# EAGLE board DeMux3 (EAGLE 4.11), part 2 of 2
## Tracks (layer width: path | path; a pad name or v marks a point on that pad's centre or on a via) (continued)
N$50  (via drill 0.61) (continued)
  Top 0.381: v198.75,48.9 198.75,90.81 v199.39,91.44
  Bottom 0.381: v198.75,48.9 216.53,48.9 217.81,50.16 IC9.5 | v199.39,91.44 202.56,91.44 205.1,93.98 R72.1
N$51  (via drill 0.61)
  Top 0.381: v198.12,47.62 197.49,48.26 v197.49,91.44
  Bottom 0.381: v198.12,47.62 217.81,47.62 220.34,50.16 IC9.6 | v197.49,91.44 198.75,92.71 201.29,92.71 202.56,93.98 R73.1
N$52  (via drill 0.61)
  Top 0.381: v300.99,97.16 303.53,94.61 303.53,90.81 304.8,89.53 R16.2 | v257.81,102.87 257.81,128.91 259.08,130.18 IDE.31
  Bottom 0.381: v300.99,97.16 299.08,99.06 292.74,99.06 292.1,99.69 292.1,102.87 v257.81,102.87
N$53  (via drill 0.61)
  Top 0.381: v302.26,119.38 302.26,116.84 306.07,113.03 306.07,93.34 304.8,92.08 R15.2 | v266.7,122.56 264.16,125.09 264.16,130.18 IDE.27
  Bottom 0.381: v302.26,119.38 299.08,122.56 v266.7,122.56
N$54  (via drill 0.61)
  Top 0.381: v300.99,125.09 300.99,116.84 303.53,114.3 303.53,95.89 304.8,94.61 R14.2 | v268.61,128.27 266.7,130.18 IDE.25
  Bottom 0.381: v300.99,125.09 297.81,128.27 v268.61,128.27
N$55  (via drill 0.61)
  Top 0.381: v302.26,109.86 v302.26,97.79 | v270.51,114.3 270.51,128.91 269.24,130.18 IDE.23
  Bottom 0.381: v302.26,97.79 302.89,97.79 304.17,96.52 R13.2 | v302.26,109.86 297.81,114.3 v270.51,114.3
N$56  (via drill 0.61)
  Top 0.381: v300.99,99.06 300.99,111.12 300.36,111.76 300.36,114.94 299.72,115.57 299.72,128.91 300.36,129.54 v300.36,130.81
  Bottom 0.381: v300.99,99.06 304.17,99.06 R12.2 | v300.36,130.81 299.08,132.08 273.69,132.08 272.42,130.81 IDE.21
N$57  (via drill 0.61)
  Top 0.381: v197.49,45.72 196.22,46.99 v196.22,75.56 | v200.03,79.38 200.66,80.01 200.66,93.34 R74.1
  Bottom 0.381: v197.49,45.72 218.44,45.72 222.88,50.16 IC9.7 | v196.22,75.56 v200.03,79.38
N$58  (via drill 0.61)
  Top 0.381: v245.11,123.19 245.11,93.34 250.19,88.27 250.19,71.12 248.92,69.85 IC12.7 | v317.5,129.54 320.04,132.08 320.04,133.99 R97.1
  Bottom 0.381: v245.11,123.19 249.56,127.64 266.06,127.64 267.97,129.54 v317.5,129.54
N$59  (via drill 0.61)
  Top 0.381: v242.57,85.09 242.57,74.93 243.84,73.66 243.84,69.85 IC12.5
  Bottom 0.381: v242.57,85.09 242.57,87.63 233.04,87.63 226.69,93.98 R96.1
N$60  (via drill 0.61)
  Top 0.381: v241.3,64.14 241.3,67.31 IC12.4 | v246.38,64.14 247.65,65.41 v247.65,83.82
  Bottom 0.381: v241.3,64.14 v246.38,64.14 | v247.65,83.82 238.76,92.71 230.5,92.71 229.24,93.98 R95.1
N$61  (via drill 0.61)
  Top 0.381: v236.22,71.75 236.22,71.12 234.95,69.85 234.95,66.67 236.85,66.67 238.12,67.94 IC12.3 | v231.14,71.75 232.41,73.03 232.41,90.17 231.14,91.44 231.14,93.34 R94.1
  Bottom 0.381: v236.22,71.75 v231.14,71.75
N$62
  Top 0.381: IC12.2 236.22,69.85 237.49,71.12 237.49,94.61 236.85,95.25 233.68,95.25 233.68,94.61 R93.1
N$63
  Top 0.381: IC12.1 233.68,69.85 234.95,71.12 234.95,92.08 236.22,93.34 R92.1
N$64  (via drill 0.61)
  Top 0.381: v236.22,80.64 236.22,77.47 IC12.15 | v241.3,85.72 241.94,86.36 241.94,129.54 236.85,134.62 R91.1
  Bottom 0.381: v236.22,80.64 237.49,81.92 237.49,85.72 v241.3,85.72
N$65  (via drill 0.61)
  Top 0.381: v209.55,95.25 209.55,93.34 210.82,92.08 210.82,77.47 IC10.15
  Bottom 0.381: v209.55,95.25 200.03,95.25 198.75,93.98 R75.1
N$66  (via drill 0.61)
  Top 0.381: v209.55,88.9 209.55,71.12 208.28,69.85 IC10.1
  Bottom 0.381: v209.55,88.9 194.31,88.9 193.68,89.53 193.68,93.98 194.94,93.98 R76.1
N$67  (via drill 0.61)
  Top 0.381: v210.82,73.66 210.82,69.85 IC10.2 | v214.63,74.3 214.63,95.89 207.01,103.5 207.01,132.72 208.28,133.99 R77.1
  Bottom 0.381: v210.82,73.66 211.46,74.3 v214.63,74.3
N$68  (via drill 0.61)
  Top 0.381: v213.36,65.41 213.36,67.31 IC10.3 | v193.68,65.41 v193.68,107.95 | v209.55,111.76 209.55,132.72 210.82,133.99 R78.1
  Bottom 0.381: v193.68,65.41 v213.36,65.41 | v193.68,107.95 197.49,111.76 v209.55,111.76
N$69  (via drill 0.61)
  Top 0.381: v192.41,66.67 v192.41,84.45 | v217.17,87.63 217.17,132.08 214.63,134.62 214,134.62 R79.1
  Bottom 0.381: v192.41,66.67 214,66.67 215.26,67.94 IC10.4 | v192.41,84.45 195.58,87.63 v217.17,87.63
N$70  (via drill 0.61)
  Top 0.381: v218.44,73.03 218.44,69.85 IC10.5 | v191.13,72.39 190.5,73.03 v190.5,121.92
  Bottom 0.381: v218.44,73.03 212.09,73.03 211.46,72.39 v191.13,72.39 | v190.5,121.92 198.75,130.18 217.17,130.18 220.98,133.99 R80.1
N$71  (via drill 0.61)
  Top 0.381: v220.98,61.59 220.98,67.31 IC10.6 | v177.8,83.19 v177.8,75.56 | v191.77,89.53 191.77,132.72 196.22,137.16 223.52,137.16 223.52,135.25 R81.1
  Bottom 0.381: v220.98,61.59 209.55,61.59 207.01,64.14 189.23,64.14 v177.8,75.56 | v177.8,83.19 184.15,89.53 v191.77,89.53
N$72
  Top 0.381: IC10.7 223.52,69.85 223.52,72.39 222.25,73.66 222.25,92.08 223.52,93.34 R82.1
N$73
  Top 0.381: R83.1 221.62,93.98 222.88,95.25 227.33,95.25 227.33,52.07 230.5,48.9 234.95,48.9 234.95,55.88 236.22,57.15 IC11.15
N$74  (via drill 0.61)
  Top 0.381: v231.14,56.52 231.14,54.61 233.68,52.07 IC11.1 | v213.36,62.87 212.09,64.14 212.09,92.08 213.36,93.34 R84.1
  Bottom 0.381: v231.14,56.52 224.79,62.87 v213.36,62.87
N$75  (via drill 0.61)
  Top 0.381: v194.94,90.17 194.94,39.37 200.66,33.66 200.66,3.17 210.82,3.17 213.36,5.71 213.36,10.79 229.87,27.3 229.87,40.64 238.76,49.53 IC11.3
  Bottom 0.381: v194.94,90.17 203.84,90.17 207.65,93.98 R86.1
N$76  (via drill 0.61)
  Top 0.381: v237.49,61.59 237.49,53.34 236.22,52.07 IC11.2 | v210.19,64.14 207.01,67.31 v207.01,90.81
  Bottom 0.381: v237.49,61.59 234.95,64.14 v210.19,64.14 | v207.01,90.81 210.19,93.98 R85.1
N$77  (via drill 0.61)
  Top 0.381: v186.69,104.14 187.96,102.87 v187.96,44.45 | v232.41,40.64 241.3,49.53 IC11.4
  Bottom 0.381: v186.69,104.14 186.69,108.58 197.49,119.38 234.95,119.38 234.95,135.25 234.31,135.89 227.97,135.89 226.69,134.62 R87.1 | v187.96,44.45 191.77,40.64 v232.41,40.64
N$78  (via drill 0.61)
  Top 0.381: v229.87,51.44 229.87,94.61 227.33,97.16 227.33,132.72 228.6,133.99 R88.1
  Bottom 0.381: v229.87,51.44 232.41,48.9 241.94,48.9 243.21,50.16 IC11.5
N$79  (via drill 0.61)
  Top 0.381: v238.12,96.52 238.12,127 231.14,133.99 R89.1 | v262.25,92.71 265.43,89.53 v265.43,58.42 | v248.92,55.24 246.38,52.7 246.38,52.07 IC11.6
  Bottom 0.381: v238.12,96.52 241.94,92.71 v262.25,92.71 | v265.43,58.42 262.89,55.88 257.18,55.88 255.91,54.61 252.73,54.61 252.09,55.24 v248.92,55.24
N$80  (via drill 0.61)
  Top 0.381: v186.69,54.61 184.15,57.15 v184.15,90.81
  Bottom 0.381: v186.69,54.61 225.43,54.61 227.33,52.7 247.01,52.7 248.28,51.44 IC11.7 | v184.15,90.81 180.97,93.98 178.44,93.98 176.53,95.89 176.53,107.95 178.44,107.95 193.68,123.19 217.81,123.19 227.97,133.35 231.78,133.35 233.04,134.62 R90.1
N$81  (via drill 0.61)
  Top 0.381: v140.97,92.08 140.97,85.09 141.6,84.45 141.6,80.64 142.24,80.01 IC8.5
  Bottom 0.381: v140.97,92.08 140.34,92.71 139.06,92.71 137.79,93.98 R127.1
N$82
  Top 0.381: IC8.4 139.7,80.01 138.43,81.28 138.43,92.08 139.7,93.34 R126.1
N$83
  Top 0.381: IC8.3 137.16,80.01 135.89,81.28 135.89,90.81 138.43,93.34 138.43,94.61 139.06,95.25 142.24,95.25 142.24,94.61 R125.1
N$84  (via drill 0.61)
  Top 0.381: v133.35,95.25 133.35,81.28 134.62,80.01 IC8.2
  Bottom 0.381: v133.35,95.25 142.88,95.25 144.15,93.98 R124.1
N$85  (via drill 0.61)
  Top 0.381: v130.81,95.89 130.81,81.28 132.08,80.01 IC8.1
  Bottom 0.381: v130.81,95.89 131.44,96.52 144.15,96.52 146.69,93.98 R123.1
N$86  (via drill 0.61)
  Top 0.381: v128.27,88.27 128.27,124.46 v136.53,132.72
  Bottom 0.381: v128.27,88.27 132.72,88.27 133.99,87 IC8.15 | v136.53,132.72 137.16,133.35 145.41,133.35 146.69,134.62 R122.1
N$87
  Top 0.381: R121.1 144.78,133.99 152.4,126.36 152.4,106.05 160.02,98.42 160.02,55.88 156.84,52.7 147.32,52.7 147.32,57.15 IC7.7
N$88  (via drill 0.61)
  Top 0.381: v148.59,84.45 148.59,87.63 149.86,88.9 149.86,126.36 142.24,133.99 R120.1 | v152.4,81.92 151.13,80.64 151.13,73.66 148.59,71.12 148.59,63.5 144.78,59.69 IC7.6
  Bottom 0.381: v148.59,84.45 149.86,84.45 v152.4,81.92
N$89  (via drill 0.61)
  Top 0.381: v148.59,135.89 161.93,122.56 161.93,114.3 168.91,107.31 168.91,60.33 159.38,50.8 142.24,50.8 142.24,57.15 IC7.5
  Bottom 0.381: v148.59,135.89 141.6,135.89 140.34,134.62 R119.1
N$90  (via drill 0.61)
  Top 0.381: v143.51,100.97 143.51,127.64 137.16,133.99 R118.1 | v157.48,92.08 v157.48,62.87
  Bottom 0.381: v143.51,100.97 144.78,99.69 149.86,99.69 v157.48,92.08 | v157.48,62.87 151.13,56.52 141.6,56.52 140.34,57.78 IC7.4
N$91  (via drill 0.61)
  Top 0.381: v98.42,55.24 v98.42,92.08
  Bottom 0.381: v98.42,55.24 133.99,55.24 136.53,57.78 IC7.3 | v98.42,92.08 116.84,92.08 118.75,93.98 R117.1
N$92  (via drill 0.61)
  Top 0.381: v133.35,67.94 133.35,60.96 134.62,59.69 IC7.2 | v111.76,72.39 107.95,76.2 v107.95,96.52 | v120.65,96.52 121.92,95.25 121.92,94.61 R116.1
  Bottom 0.381: v133.35,67.94 128.91,72.39 v111.76,72.39 | v107.95,96.52 v120.65,96.52
N$93  (via drill 0.61)
  Top 0.381: v106.05,60.96 101.6,65.41 v101.6,93.34
  Bottom 0.381: v106.05,60.96 129.54,60.96 131.44,59.05 IC7.1 | v101.6,93.34 103.5,95.25 122.56,95.25 123.83,93.98 R115.1
N$94  (via drill 0.61)
  Top 0.381: v142.88,74.93 142.88,74.3 135.25,66.67 IC7.15 | v154.31,85.72 153.67,86.36 v153.67,92.08
  Bottom 0.381: v142.88,74.93 144.78,76.83 151.13,76.83 154.31,80.01 v154.31,85.72 | v153.67,92.08 147.32,98.42 131.44,98.42 129.54,96.52 129.54,94.61 132.08,94.61 R114.1
N$95  (via drill 0.61)
  Top 0.381: v84.45,72.39 84.45,111.76 106.68,133.99 R98.1
  Bottom 0.381: v84.45,72.39 84.45,62.87 85.09,62.23 87.63,62.23 88.9,60.96 104.14,60.96 108.58,65.41 IC5.15
N$96  (via drill 0.61)
  Top 0.381: v80.64,59.69 v80.64,105.41
  Bottom 0.381: v80.64,59.69 87.63,59.69 88.9,58.42 106.05,58.42 IC5.1 | v80.64,105.41 109.22,133.99 R99.1
N$97  (via drill 0.61)
  Top 0.381: v104.14,52.7 104.14,53.34 108.58,57.78 IC5.2 | v82.55,52.7 81.92,53.34 81.92,111.76 106.05,135.89 111.76,135.89 111.76,135.25 R100.1
  Bottom 0.381: v82.55,52.7 v104.14,52.7
N$98  (via drill 0.61)
  Top 0.381: v104.14,77.47 104.14,76.2 107.95,72.39 107.95,63.5 111.76,59.69 IC5.3 | v94.61,78.74 94.61,115.57 113.67,134.62 R101.1
  Bottom 0.381: v104.14,77.47 102.87,78.74 v94.61,78.74
N$99  (via drill 0.61)
  Top 0.381: v95.89,56.52 95.89,115.57 113.67,133.35 114.94,133.35 116.2,134.62 R102.1
  Bottom 0.381: v95.89,56.52 112.39,56.52 113.67,57.78 IC5.4
N$100
  Top 0.381: IC5.5 116.84,59.69 115.57,60.96 115.57,92.08 116.84,93.34 R103.1
N$101  (via drill 0.61)
  Top 0.381: v118.11,73.66 118.11,60.96 119.38,59.69 IC5.6 | v111.76,76.2 110.49,77.47 110.49,89.53 114.3,93.34 R104.1
  Bottom 0.381: v118.11,73.66 115.57,76.2 v111.76,76.2
N$102
  Top 0.381: IC5.7 121.28,57.78 120.02,56.52 110.49,56.52 110.49,59.69 105.41,64.77 105.41,73.66 102.87,76.2 102.87,93.34 107.31,97.79 111.76,97.79 111.76,94.61 R105.1
N$103
  Top 0.381: IC6.15 109.22,87.63 109.22,93.34 R106.1
N$104
  Top 0.381: IC6.1 106.68,80.01 105.41,81.28 105.41,92.08 106.68,93.34 R107.1
N$105  (via drill 0.61)
  Top 0.381: v97.16,76.2 97.16,92.71 107.95,103.5 107.95,125.09 116.2,133.35 118.75,133.35 118.75,134.62 R108.1
  Bottom 0.381: v97.16,76.2 106.68,76.2 108.58,78.11 IC6.2
N$106  (via drill 0.61)
  Top 0.381: v100.33,81.28 100.33,93.98 109.22,102.87 120.65,102.87 120.65,132.72 121.92,133.99 R109.1
  Bottom 0.381: v100.33,81.28 109.22,81.28 111.12,79.38 IC6.3
N$107  (via drill 0.61)
  Top 0.381: v150.5,81.92 151.13,82.55 151.13,126.36 143.51,133.99 143.51,135.25 142.88,135.89 124.46,135.89 124.46,135.25 R110.1
  Bottom 0.381: v150.5,81.92 132.72,81.92 127.64,76.83 116.2,76.83 114.94,78.11 IC6.4
N$108
  Top 0.381: IC6.5 116.84,80.01 118.11,81.28 118.11,95.89 125.73,103.5 125.73,128.91 131.44,134.62 R111.1
N$109  (via drill 0.61)
  Top 0.381: v113.67,81.28 113.03,81.92 113.03,90.81 115.57,93.34 115.57,95.89 123.19,103.5 v123.19,126.36
  Bottom 0.381: v113.67,81.28 116.84,81.28 118.75,79.38 IC6.6 | v123.19,126.36 130.18,133.35 132.72,133.35 133.99,134.62 R112.1
N$110  (via drill 0.61)
  Top 0.381: v120.65,92.08 120.65,85.09 121.92,83.82 121.92,80.01 IC6.7
  Bottom 0.381: v120.65,92.08 121.28,92.71 132.72,92.71 133.99,93.98 R113.1
N$111
  Top 0.381: IC1.15 25.4,87.63 25.4,132.72 24.13,133.99 R128.1
N$112
  Top 0.381: IC1.1 22.86,80.01 21.59,81.28 21.59,133.99 23.5,135.89 34.29,135.89 34.29,135.25 R129.1
N$113
  Top 0.381: IC1.2 26.04,79.38 27.3,80.64 28.57,80.64 29.21,80.01 29.21,77.47 29.84,76.83 34.29,76.83 34.29,93.34 R130.1
N$114
  Top 0.381: IC1.3 27.3,78.11 26.04,76.83 24.13,76.83 24.13,93.34 R131.1
N$115
  Top 0.381: IC1.4 30.48,80.01 31.75,81.28 31.75,99.69 35.56,103.5 35.56,132.72 36.83,133.99 R132.1
N$116
  Bottom 0.381: IC1.5 32.38,78.11 31.11,76.83 21.59,76.83 19.05,79.38 19.05,133.35 50.16,133.35 51.44,134.62 R133.1
N$117  (via drill 0.61)
  Top 0.381: v39.37,88.27 39.37,76.83 37.47,76.83 36.2,78.11 IC1.6
  Bottom 0.381: v39.37,88.27 45.09,93.98 51.44,93.98 R134.1
N$118
  Top 0.381: IC1.7 38.1,80.01 36.83,81.28 36.83,93.34 R135.1
N$119
  Top 0.381: IC4.15 50.8,87.63 53.34,90.17 53.34,132.72 54.61,133.99 R136.1
N$120
  Top 0.381: IC4.3 53.98,79.38 57.15,82.55 57.15,93.34 R139.1
N$121
  Top 0.381: IC4.2 50.8,80.01 54.61,83.82 54.61,93.34 56.52,95.25 64.77,95.25 64.77,94.61 R138.1
N$122
  Top 0.381: IC4.1 48.26,80.01 49.53,81.28 49.53,111.12 50.8,112.39 50.8,131.44 53.34,133.99 53.34,135.25 53.98,135.89 64.77,135.89 64.77,135.25 R137.1
OPR
  Top 0.381: R58.2 325.12,123.83 326.39,122.56 326.39,114.94 327.66,113.67 D40.16
PAUSE
  Top 0.381: R60.2 345.44,123.83 347.98,121.28 347.98,116.2 D40.31
PB-A0  (via drill 0.61)
  Top 0.381: v177.8,90.17 179.07,91.44 v179.07,95.25 | v184.15,93.98 v184.15,96.52 | 252.73,111.12 254,112.39 SLOT1.35 | 252.73,111.12 252.73,97.16 254,95.89 SLOT2.35 | 252.73,111.12 252.73,128.91 254,130.18 IDE.35
  Bottom 0.381: v177.8,90.17 175.26,90.17 175.26,55.24 191.13,39.37 234.31,39.37 235.59,38.1 XESS.57 | v179.07,95.25 182.25,95.25 183.51,93.98 v184.15,93.98 | v184.15,96.52 187.32,99.69 245.11,99.69 248.28,96.52 252.09,96.52 253.37,95.25 SLOT2.35
PB-A1  (via drill 0.61)
  Top 0.381: IDE.33 256.54,130.18 256.54,118.75 255.27,117.47 255.27,114.94 256.54,113.67 SLOT1.33 256.54,112.39 256.54,99.69 255.27,98.42 255.27,97.16 256.54,95.89 SLOT2.33 256.54,94.61 262.89,88.27 262.89,81.92 260.35,79.38 260.35,43.81 v259.71,43.18
  Bottom 0.381: v259.71,43.18 255.27,43.18 252.73,40.64 241.94,40.64 239.4,38.1 XESS.56
PB-A2  (via drill 0.61)
  Top 0.381: v251.46,42.55 251.46,38.73 XESS.51 | v259.08,44.45 259.08,80.64 260.35,81.92 260.35,89.53 255.27,94.61 255.27,95.89 254,97.16 SLOT2.36 254,98.42 255.27,99.69 255.27,113.67 254,114.94 SLOT1.36 254,116.2 254,117.47 255.27,118.75 255.27,131.44 254,132.72 IDE.36
  Bottom 0.381: v251.46,42.55 253.37,44.45 v259.08,44.45
PB-A3  (via drill 0.61)
  Top 0.381: SLOT1.38 251.46,114.94 250.19,113.67 250.19,112.39 251.46,111.12 251.46,98.42 SLOT2.38 251.46,97.16 252.73,95.89 252.73,94.61 257.81,89.53 v257.81,59.69 | v255.27,58.42 255.27,56.52 252.73,53.98 252.73,51.44 254,50.16 254,38.73 XESS.50
  Bottom 0.381: v255.27,58.42 256.54,59.69 v257.81,59.69
PB-A4
  Top 0.381: SLOT1.39 248.92,112.39 248.92,107.31 247.65,106.05 247.65,97.16 248.92,95.89 SLOT2.39
  Bottom 0.381: XESS.70 235.59,82.55 224.79,93.34 224.79,97.79 245.75,97.79 248.28,95.25 SLOT2.39
PB-D0  (via drill 0.61)
  Top 0.381: IDE.17 276.86,130.18 275.59,128.91 275.59,114.94 276.86,113.67 SLOT1.17 276.86,112.39 276.86,99.69 275.59,98.42 275.59,97.16 276.86,95.89 SLOT2.17 276.86,94.61 v276.86,91.44
  Bottom 0.381: v276.86,91.44 248.92,91.44 248.92,89.53 249.56,88.9 250.19,88.9 250.19,81.92 249.56,81.28 240.66,81.28 239.4,82.55 XESS.71
PB-D1
  Top 0.381: IDE.15 279.4,130.18 279.4,117.47 278.13,116.2 278.13,114.94 279.4,113.67 SLOT1.15 279.4,112.39 279.4,99.69 278.13,98.42 278.13,97.16 279.4,95.89 SLOT2.15 279.4,94.61 279.4,85.72 278.13,84.45 278.13,81.92 279.4,80.64 279.4,38.73 XESS.40
PB-D2
  Top 0.381: IDE.13 281.94,130.18 281.94,117.47 280.67,116.2 280.67,114.94 281.94,113.67 SLOT1.13 281.94,112.39 281.94,99.69 280.67,98.42 280.67,93.34 | 280.67,93.34 280.67,81.92 281.94,80.64 281.94,38.73 XESS.39 | 280.67,93.34 281.94,94.61 SLOT2.13
PB-D3
  Top 0.381: IDE.11 284.48,130.18 284.48,117.47 283.21,116.2 283.21,114.94 284.48,113.67 SLOT1.11 284.48,112.39 284.48,99.69 283.21,98.42 283.21,97.16 284.48,95.89 SLOT2.11 284.48,94.61 284.48,84.45 283.21,83.19 283.21,81.92 284.48,80.64 284.48,38.73 XESS.38
PB-D4  (via drill 0.61)
  Top 0.381: SLOT2.9 287.02,95.89 285.75,97.16 285.75,98.42 287.02,99.69 287.02,112.39 SLOT1.9 287.02,113.67 285.75,114.94 285.75,116.2 287.02,117.47 287.02,130.18 IDE.9 | v293.37,91.44 293.37,67.31 292.1,66.04 292.1,38.73 XESS.35
  Bottom 0.381: v293.37,91.44 287.65,91.44 287.02,92.08 287.02,94.61 SLOT2.9
PB-D5  (via drill 0.61)
  Top 0.381: IDE.7 289.56,130.18 289.56,117.47 288.29,116.2 288.29,114.94 289.56,113.67 SLOT1.7 289.56,112.39 289.56,99.69 288.29,98.42 288.29,97.16 289.56,95.89 SLOT2.7 289.56,94.61 v289.56,87.63 | v261.62,87.63 261.62,83.19 XESS.80
  Bottom 0.381: v261.62,87.63 v289.56,87.63
PB-D6  (via drill 0.61)
  Top 0.381: IDE.5 292.1,130.18 292.1,117.47 290.83,116.2 290.83,114.94 292.1,113.67 SLOT1.5 292.1,112.39 292.1,99.69 290.83,98.42 290.83,97.16 292.1,95.89 SLOT2.5 292.1,94.61 v292.1,88.9 | v264.16,88.9 264.16,83.19 XESS.81
  Bottom 0.381: v264.16,88.9 v292.1,88.9
PB-D7
  Top 0.381: XESS.10 297.18,83.19 297.18,85.72 295.91,87 295.91,93.34 294.64,94.61 SLOT2.3 294.64,95.89 293.37,97.16 293.37,98.42 294.64,99.69 294.64,112.39 SLOT1.3 294.64,113.67 293.37,114.94 293.37,116.2 294.64,117.47 294.64,130.18 IDE.3
PB-D8  (via drill 0.61)
  Top 0.381: v308.61,99.69 311.15,97.16 311.15,40.01 312.42,38.73 XESS.27 | SLOT2.4 294.64,98.42 295.91,99.69 v295.91,102.87 295.91,113.67 294.64,114.94 SLOT1.4 294.64,116.2 295.91,117.47 295.91,131.44 294.64,132.72 IDE.4
  Bottom 0.381: v308.61,99.69 305.44,102.87 v295.91,102.87
PB-D9  (via drill 0.61)
  Top 0.381: v308.61,97.16 308.61,81.92 309.88,80.64 309.88,38.73 XESS.28 | SLOT2.6 292.1,98.42 293.37,99.69 v293.37,100.33 293.37,113.67 292.1,114.94 SLOT1.6 292.1,116.2 293.37,117.47 293.37,131.44 292.1,132.72 IDE.6
  Bottom 0.381: v308.61,97.16 305.44,100.33 v293.37,100.33
PB-D10  (via drill 0.61)
  Top 0.381: v304.8,41.91 304.8,41.27 307.34,38.73 XESS.29 | v288.93,43.18 285.75,46.35 v285.75,93.98 | SLOT2.8 289.56,98.42 290.83,99.69 290.83,113.67 289.56,114.94 SLOT1.8 289.56,116.2 290.83,117.47 290.83,131.44 289.56,132.72 IDE.8
  Bottom 0.381: v304.8,41.91 303.53,43.18 v288.93,43.18 | v285.75,93.98 285.75,96.52 287.65,96.52 288.93,97.79 SLOT2.8
PB-D11  (via drill 0.61)
  Top 0.381: v299.72,105.41 299.72,97.79 298.45,96.52 298.45,67.31 299.72,66.04 299.72,38.73 XESS.32 | SLOT2.10 287.02,98.42 288.29,99.69 v288.29,105.41 288.29,113.67 287.02,114.94 SLOT1.10 287.02,116.2 288.29,117.47 288.29,131.44 287.02,132.72 IDE.10
  Bottom 0.381: v299.72,105.41 v288.29,105.41
PB-D12  (via drill 0.61)
  Top 0.381: v297.18,44.45 297.18,38.73 XESS.33 | v289.56,44.45 288.29,45.72 v288.29,85.09 | v283.21,85.09 v283.21,93.98 | SLOT2.12 284.48,98.42 285.75,99.69 285.75,113.67 284.48,114.94 SLOT1.12 284.48,116.2 285.75,117.47 285.75,131.44 284.48,132.72 IDE.12
  Bottom 0.381: v289.56,44.45 v297.18,44.45 | v288.29,85.09 v283.21,85.09 | v283.21,93.98 283.21,97.79 283.85,97.79 SLOT2.12
PB-D13  (via drill 0.61)
  Top 0.381: v294.64,45.72 294.64,38.73 XESS.34 | v278.13,45.72 v278.13,78.74 | v275.59,78.74 v275.59,92.71 | SLOT2.14 281.94,98.42 283.21,99.69 283.21,113.67 281.94,114.94 SLOT1.14 281.94,116.2 283.21,117.47 283.21,131.44 281.94,132.72 IDE.14
  Bottom 0.381: v278.13,45.72 v294.64,45.72 | v278.13,78.74 v275.59,78.74 | v275.59,92.71 278.76,92.71 280.67,94.61 280.67,97.79 281.31,97.79 SLOT2.14
PB-D14  (via drill 0.61)
  Top 0.381: v290.83,85.09 290.83,40.01 289.56,38.73 XESS.36 | v278.13,86.36 v278.13,93.98 | SLOT2.16 279.4,98.42 280.67,99.69 280.67,113.67 279.4,114.94 SLOT1.16 279.4,116.2 280.67,117.47 280.67,131.44 279.4,132.72 IDE.16
  Bottom 0.381: v290.83,85.09 289.56,86.36 v278.13,86.36 | v278.13,93.98 278.13,97.79 278.76,97.79 SLOT2.16
PB-D15  (via drill 0.61)
  Top 0.381: SLOT2.18 276.86,98.42 278.13,99.69 278.13,113.67 276.86,114.94 SLOT1.18 276.86,116.2 278.13,117.47 278.13,131.44 276.86,132.72 IDE.18 | v278.13,41.91 276.86,43.18 v276.86,69.22 | v271.78,70.48 271.78,80.64 273.05,81.92 273.05,92.08 v274.32,93.34
  Bottom 0.381: v278.13,41.91 280.67,39.37 285.12,39.37 286.38,38.1 XESS.37 | v276.86,69.22 275.59,70.48 v271.78,70.48 | v274.32,93.34 275.59,94.61 275.59,97.79 276.23,97.79 SLOT2.18
PB-RD#  (via drill 0.61)
  Top 0.381: v311.15,108.58 311.15,98.42 314.96,94.61 R14.1 | v227.33,43.18 227.33,40.01 226.06,38.73 XESS.61 | v261.62,45.72 262.89,46.99 v262.89,69.22 | v266.7,70.48 267.97,71.75 267.97,93.34 266.7,94.61 SLOT2.25 266.7,95.89 265.43,97.16 265.43,98.42 266.7,99.69 266.7,112.39 SLOT1.25
  Bottom 0.381: v311.15,108.58 277.5,108.58 274.32,111.76 268.61,111.76 267.33,113.03 SLOT1.25 | v227.33,43.18 229.87,45.72 v261.62,45.72 | v262.89,69.22 264.16,70.48 v266.7,70.48
PB-WR#  (via drill 0.61)
  Top 0.381: v312.42,107.31 312.42,99.69 314.96,97.16 R13.1 | SLOT1.23 269.24,112.39 v269.24,106.68 269.24,99.69 267.97,98.42 267.97,97.16 269.24,95.89 SLOT2.23 | v217.81,43.18 222.88,38.1 XESS.62 | v179.07,58.42 179.07,90.17 180.34,91.44 180.34,94.61 181.61,95.89 181.61,106.05 183.51,107.95 v187.96,107.95
  Bottom 0.381: v312.42,107.31 273.05,107.31 272.42,106.68 v269.24,106.68 189.23,106.68 v187.96,107.95 | v217.81,43.18 194.31,43.18 v179.07,58.42
PC0
  Top 0.381: R98.2 106.68,123.83 106.68,116.2 E40.1
PC1
  Top 0.381: R103.2 116.84,104.78 116.84,112.39 E40.10
PC2
  Top 0.381: R108.2 119.38,123.83 119.38,116.2 E40.11
PC3
  Top 0.381: R113.2 134.62,104.78 134.62,112.39 E40.24
PC4
  Top 0.381: R118.2 137.16,123.83 137.16,116.2 E40.25
PC5
  Top 0.381: R123.2 147.32,104.78 147.32,112.39 E40.34
PC6
  Top 0.381: R67.2 195.58,123.83 195.58,116.2 F40.1
PC7
  Top 0.381: R72.2 205.74,104.78 205.74,112.39 F40.10
PC8
  Top 0.381: R77.2 208.28,123.83 208.28,116.2 F40.11
PC9
  Top 0.381: R82.2 223.52,104.78 223.52,112.39 F40.24
PC10
  Top 0.381: R87.2 226.06,123.83 226.06,116.2 F40.25
PC11
  Top 0.381: R92.2 236.22,104.78 236.22,112.39 F40.34
RCK  (via drill 0.61)  (1 unrouted)
  Top 0.381: 326.39,57.15 326.39,73.66 327.66,74.93 IC16.12 | 326.39,57.15 326.39,17.78 322.58,13.97 IC19.6 | IC9.12 218.44,59.69 217.17,60.96 217.17,73.66 218.44,74.93 IC10.12 | v242.57,73.03 242.57,60.96 243.84,59.69 IC11.12 | v185.42,100.33 186.69,99.06 v186.69,80.64 | v322.58,57.15 326.39,57.15 | v280.67,73.03 v280.67,57.15 | v128.91,87 129.54,87.63 129.54,96.52 130.18,97.16 143.51,97.16 143.51,88.9 142.24,87.63 IC8.12
  Bottom 0.381: IC10.12 219.07,75.56 221.62,73.03 v242.57,73.03 v280.67,73.03 296.55,73.03 299.08,75.56 IC13.12 | IC12.12 243.21,76.83 241.94,78.11 220.34,78.11 219.07,76.83 IC10.12 | v185.42,100.33 182.25,100.33 180.97,99.06 SV1.7 | v186.69,80.64 214,80.64 217.81,76.83 IC10.12 | v280.67,57.15 v322.58,57.15 | IC1.12 33.66,85.72 34.92,84.45 56.52,84.45 57.78,85.72 IC4.12 59.05,87 60.33,88.27 114.94,88.27 116.2,87 IC6.12 117.47,87 118.75,88.27 126.36,88.27 127.64,87 v128.91,87 | IC5.12 117.47,65.41 118.75,64.14 140.34,64.14 141.6,65.41 IC7.12 142.88,66.67 146.05,69.85 151.13,69.85 166.37,85.09 166.37,88.27 161.29,88.27 | 161.29,88.27 144.15,88.27 142.88,87 IC8.12 | 161.29,88.27 168.91,95.89 168.91,98.42 167.64,98.42 SV2.7
RESET-TRIG#  (via drill 0.61)
  Top 0.381: v298.45,29.21 298.45,11.43 297.81,10.79 297.81,3.81 288.29,3.81 280.67,11.43 280.67,26.04 281.94,27.3 R23.1 | v337.82,29.21 341.63,33.02 v341.63,76.2
  Bottom 0.381: v298.45,29.21 v337.82,29.21 | v341.63,76.2 335.28,82.55 325.75,82.55 XESS.21
RS232-RD  (via drill 0.61)
  Top 0.381: D1.C 325.12,5.71 325.12,6.99 R2.1 324.49,7.62 318.13,7.62 316.23,9.53 316.23,24.77 313.69,27.3 v313.69,39.37
  Bottom 0.381: v313.69,39.37 304.17,39.37 302.89,38.1 XESS.31
RS232-RTS  (via drill 0.61)
  Top 0.381: v252.73,39.37 252.73,29.84 251.46,28.57 R3.1 | v256.54,41.91 257.81,43.18 v257.81,51.44 | v300.99,55.88 302.26,54.61 v302.26,48.26 | v312.42,45.72 314.96,43.18 314.96,38.73 XESS.26
  Bottom 0.381: v252.73,39.37 255.27,41.91 v256.54,41.91 | v257.81,51.44 260.99,54.61 290.19,54.61 291.46,55.88 v300.99,55.88 | v302.26,48.26 304.8,45.72 v312.42,45.72
RS232-TD  (via drill 0.61)
  Top 0.381: v271.78,31.11 276.86,36.2 276.86,37.47 XESS.41
  Bottom 0.381: v271.78,31.11 248.92,31.11 248.92,26.04 R1.1
RTS
  Bottom 0.381: IC3.7 240.66,13.34 239.4,14.61 231.14,14.61 229.24,16.51 193.04,16.51 192.41,17.14 191.13,17.14 189.23,15.24 X1.8 189.87,14.61 192.41,14.61 196.85,10.16 RS-232.5
RUN
  Bottom 0.381: R61.2 347.98,123.83 347.98,116.84 348.62,116.84 349.88,115.57 D40.33
RXD
  Bottom 0.381: IC3.8 243.21,12.06 241.94,10.79 212.09,10.79 210.19,12.7 199.39,12.7 RS-232.4 196.85,12.7 195.58,12.7 192.41,15.88 X1.3
SC0
  Top 0.381: R129.2 34.29,123.83 34.29,116.2 C40.9
SC1
  Top 0.381: R131.2 24.13,104.78 24.13,112.39 C40.2
SC2
  Top 0.381: R133.2 52.07,123.83 52.07,116.2 C40.23
SC3
  Top 0.381: R135.2 36.83,104.78 36.83,112.39 C40.12
SC4
  Top 0.381: R137.2 64.77,123.83 64.77,116.2 C40.33
SCL\  (via drill 0.61)  (1 unrouted)
  Top 0.381: v297.18,35.56 297.18,21.59 IC17.12 | v202.56,35.56 202.56,60.96 203.84,62.23 v203.84,78.74 | v208.28,79.38 208.28,92.08 207.01,93.34 v207.01,100.97 | v170.18,98.42 v170.18,67.94
  Bottom 0.381: v202.56,35.56 v297.18,35.56 | v203.84,78.74 204.47,79.38 v208.28,79.38 | v207.01,100.97 206.38,101.6 180.97,101.6 SV1.5 | IC14.1 31.11,41.27 32.38,42.55 48.9,42.55 50.8,40.64 59.05,40.64 IC15.1 60.33,41.27 61.59,42.55 78.11,42.55 80.01,40.64 98.42,40.64 IC18.1 99.69,41.27 100.97,42.55 117.47,42.55 119.38,40.64 126.36,40.64 IC2.1 127.64,41.27 128.91,42.55 144.78,42.55 v170.18,67.94 | v170.18,98.42 167.64,100.97 SV2.5
SCLK  (via drill 0.61)  (1 unrouted)
  Top 0.381: v163.83,57.15 163.83,94.61 165.1,95.89 SV2.10 | v269.24,15.24 267.97,16.51 267.97,19.68 265.43,22.23 v265.43,32.38 | v186.06,33.02 176.53,33.02 176.53,94.61 177.8,95.89 SV1.10
  Bottom 0.381: IC14.2 33.66,40.01 34.92,38.73 60.33,38.73 61.59,40.01 IC15.2 62.87,40.01 67.94,34.92 95.25,34.92 99.06,38.73 103.5,38.73 | 103.5,38.73 102.23,40.01 IC18.2 | 127.64,38.73 103.5,38.73 | 127.64,38.73 128.91,40.01 IC2.2 | v163.83,57.15 145.41,38.73 127.64,38.73 | v269.24,15.24 280.67,15.24 280.67,11.43 281.31,10.79 285.12,10.79 286.38,12.06 IC17.5 | v265.43,32.38 264.8,33.02 v186.06,33.02
SD-CD#  (via drill 0.61)
  Top 0.381: v341.63,1.27 271.78,1.27 v271.78,20.32 | v262.89,80.01 261.62,78.74 v261.62,53.34 | v256.54,49.53 255.27,48.26 255.27,24.77 254,23.5 R4.1
  Bottom 0.381: v341.63,1.27 344.81,1.27 347.98,4.45 J4.10 | v271.78,20.32 270.51,21.59 255.91,21.59 254.63,22.86 R4.1 | v262.89,80.01 262.89,80.64 263.52,81.28 280.04,81.28 281.31,82.55 XESS.4 | v261.62,53.34 257.81,49.53 v256.54,49.53
SD-CLK  (via drill 0.61)
  Top 0.381: v337.82,13.34 332.74,18.41 v332.74,49.53 | v275.59,49.53 274.32,50.8 274.32,61.59 273.05,62.87 273.05,80.64 274.32,81.92 XESS.1
  Bottom 0.381: v337.82,13.34 347.98,13.34 J4.5 | v275.59,49.53 v332.74,49.53
SD-CMD  (via drill 0.61)
  Top 0.381: v292.1,25.4 292.1,33.66 288.29,37.47 288.29,40.01 v285.75,42.55 | v267.97,43.18 266.7,41.91 266.7,38.73 XESS.45
  Bottom 0.381: v292.1,25.4 300.99,25.4 303.53,22.86 325.12,22.86 326.39,21.59 347.98,21.59 J4.2 | v285.75,42.55 285.12,43.18 v267.97,43.18
SD-DAT0  (via drill 0.61)
  Top 0.381: v350.52,10.16 351.15,10.79 v351.15,40.01 | v297.18,46.99 295.91,48.26 v295.91,74.3 | v224.79,74.3 224.79,78.11 226.06,79.38 226.06,81.92 XESS.66
  Bottom 0.381: v350.52,10.16 349.25,10.16 348.62,9.53 J4.7 | v351.15,40.01 346.71,44.45 299.72,44.45 v297.18,46.99 | v295.91,74.3 291.46,74.3 290.83,74.93 290.83,78.11 285.75,78.11 283.85,76.2 253.37,76.2 252.73,75.56 252.73,74.3 v224.79,74.3
SD-DAT1  (via drill 0.61)
  Top 0.381: v349.88,8.89 347.35,11.43 347.35,26.67 344.17,29.84 v344.17,52.07 | v266.7,50.8 264.16,48.26 264.16,45.09 257.81,38.73 v257.81,34.29 | v196.22,34.29 180.34,50.16 v180.34,83.19
  Bottom 0.381: v349.88,8.89 348.62,7.62 J4.8 | v344.17,52.07 291.46,52.07 290.19,50.8 v266.7,50.8 | v196.22,34.29 v257.81,34.29 | v180.34,83.19 219.71,83.19 220.34,83.82 226.69,83.82 227.97,82.55 XESS.67
SD-DAT2  (via drill 0.61)
  Top 0.381: v346.07,24.77 342.9,27.94 v342.9,53.34 | v275.59,52.07 275.59,61.59 274.32,62.87 v274.32,66.04 | v219.71,66.67 v219.71,79.38
  Bottom 0.381: v346.07,24.77 347.98,24.77 J4.9 | v342.9,53.34 291.46,53.34 290.19,52.07 v275.59,52.07 | v274.32,66.04 273.69,66.67 v219.71,66.67 | v219.71,79.38 221.62,81.28 229.24,81.28 230.5,82.55 XESS.68
SD-DAT3  (via drill 0.61)
  Top 0.381: v337.82,22.86 336.55,24.13 336.55,92.08 332.74,95.89 v332.74,110.49 | v236.22,126.36 232.41,126.36 232.41,91.44 233.68,90.17 233.68,83.19 XESS.69
  Bottom 0.381: v337.82,22.86 347.98,22.86 J4.1 | v332.74,110.49 325.75,110.49 323.85,112.39 323.85,119.38 304.17,119.38 299.72,123.83 247.65,123.83 245.75,121.92 240.66,121.92 v236.22,126.36
SD-WP  (via drill 0.61)
  Top 0.381: v328.93,26.67 327.66,25.4 327.66,17.78 323.85,13.97 v323.85,10.79 | v268.61,3.81 266.06,6.35 264.8,6.35 v264.8,6.99 | v264.16,64.14 v264.16,80.01 | v251.46,62.23 250.19,60.96 250.19,46.99 247.65,44.45 247.65,17.14 251.46,13.34 R5.1
  Bottom 0.381: v328.93,26.67 341.63,26.67 342.26,26.04 353.69,26.04 353.69,5.71 353.06,5.08 351.15,5.08 351.15,1.91 351.79,1.27 367.03,1.27 J4.12 | v323.85,10.79 323.21,10.16 304.17,10.16 297.81,3.81 v268.61,3.81 | v264.8,6.99 260.35,11.43 253.37,11.43 252.09,12.7 R5.1 | v264.16,80.01 281.31,80.01 283.85,82.55 XESS.5 | v264.16,64.14 262.25,62.23 v251.46,62.23
SDF0
  Top 0.381: A40.6 38.1,8.26 36.83,9.53 36.83,18.41 38.1,19.68 R24.1 38.1,20.95 35.56,23.5 35.56,38.1 36.83,39.37 36.83,50.16 41.27,50.16 42.55,48.9 IC14.11
SDF1
  Top 0.381: 39.37,18.41 40.64,19.68 R25.1 | 39.37,18.41 39.37,9.53 40.64,8.26 A40.8 | 39.37,18.41 39.37,45.72 40.64,46.99 IC14.12
SDF2  (via drill 0.61)
  Top 0.381: A40.10 43.18,8.26 41.91,9.53 41.91,18.41 43.18,19.68 R26.1 43.18,20.95 44.45,22.23 v44.45,45.09
  Bottom 0.381: v44.45,45.09 41.27,45.09 38.73,47.62 IC14.13
SI  (via drill 0.61)
  Top 0.381: R49.1 137.16,19.68 135.89,18.41 135.89,9.53 137.16,8.26 B40.32 | v113.03,29.21 113.03,43.18 109.22,46.99 IC18.12
  Bottom 0.381: v113.03,29.21 120.65,21.59 135.25,21.59 136.53,20.32 R49.1
SIF0
  Top 0.381: R27.1 45.72,19.68 44.45,18.41 44.45,9.53 45.72,8.26 A40.12
  Bottom 0.381: IC14.14 34.92,48.9 33.66,50.16 29.21,50.16 24.77,45.72 24.77,19.05 43.81,19.05 45.09,20.32 R27.1
SIF1
  Top 0.381: R28.1 48.26,19.68 46.99,18.41 46.99,9.53 48.26,8.26 A40.14 47.62,7.62 47.62,6.35 37.47,6.35 36.83,6.99 36.83,8.26 36.2,8.89 34.92,8.89 34.29,9.53 34.29,38.1 35.56,39.37 IC14.3
SIF2  (via drill 0.61)
  Top 0.381: R29.1 50.8,19.68 49.53,18.41 49.53,9.53 50.8,8.26 A40.16 | v36.83,29.21 36.83,38.1 38.1,39.37 IC14.4
  Bottom 0.381: v36.83,29.21 40.01,26.04 44.45,26.04 50.16,20.32 R29.1
SLOT1-CS#  (via drill 0.61)
  Top 0.381: v310.51,111.12 316.23,105.41 316.23,99.69 318.77,97.16 318.77,88.27 v316.23,85.72
  Bottom 0.381: v310.51,111.12 309.88,111.12 302.89,118.11 266.06,118.11 264.8,116.84 252.73,116.84 252.73,114.94 251.46,113.67 SLOT1.37 | v316.23,85.72 316.23,83.19 317.5,83.19 XESS.18
SLOT1-IRQ
  Top 0.381: R21.1 271.78,104.78 273.05,103.5 273.05,93.34 271.78,92.08 271.78,83.19 XESS.84
SLOT2-CS#  (via drill 0.61)
  Top 0.381: v318.77,62.87 318.77,77.47 320.04,78.74 320.04,81.92 XESS.19 | v275.59,63.5 275.59,76.83 v274.32,78.11 | v255.91,78.74 252.73,81.92 252.73,92.71 251.46,93.98 251.46,94.61 SLOT2.37
  Bottom 0.381: v318.77,62.87 288.29,62.87 287.65,63.5 v275.59,63.5 | v274.32,78.11 273.69,78.74 v255.91,78.74
SLOT2-IRQ  (via drill 0.61)
  Top 0.381: v250.19,90.17 250.19,103.5 248.92,104.78 R22.1
  Bottom 0.381: v250.19,90.17 254,86.36 271.14,86.36 271.78,85.72 271.78,83.82 271.14,83.82 269.88,82.55 XESS.83
SR0  (via drill 0.61)
  Top 0.381: R30.1 53.34,19.68 52.07,18.41 52.07,9.53 53.34,8.26 A40.18 | v40.64,37.47 40.64,39.37 IC14.5
  Bottom 0.381: v40.64,37.47 45.72,37.47 52.07,31.11 52.07,20.95 53.34,20.95 R30.1
SR1
  Top 0.381: 54.61,18.41 55.88,19.68 R31.1 | 54.61,18.41 54.61,9.53 55.88,8.26 A40.20 | 54.61,18.41 54.61,50.16 45.09,50.16 44.45,49.53 44.45,46.99 43.18,45.72 43.18,41.91 IC14.6
SR2  (via drill 0.61)
  Top 0.381: 62.23,18.41 63.5,19.68 R32.1 | 62.23,18.41 62.23,9.53 63.5,8.26 A40.26 | v64.77,45.09 63.5,43.81 63.5,32.38 62.23,31.11 62.23,18.41
  Bottom 0.381: v64.77,45.09 69.22,45.09 71.75,47.62 IC15.11
SR3
  Top 0.381: 64.77,18.41 66.04,19.68 R33.1 | 64.77,18.41 64.77,9.53 66.04,8.26 A40.28 | 64.77,18.41 64.77,31.11 66.04,32.38 66.04,50.16 67.94,50.16 69.22,48.9 IC15.12
SR4
  Top 0.381: 67.31,18.41 68.58,19.68 R34.1 | 67.31,18.41 67.31,9.53 68.58,8.26 A40.30 | 67.31,18.41 67.31,31.11 68.58,32.38 68.58,45.72 67.31,46.99 IC15.13
SR5
  Top 0.381: A40.34 73.66,8.26 72.39,9.53 72.39,18.41 73.66,19.68 R35.1 73.66,20.95 76.2,23.5 76.2,51.44 66.04,51.44 64.77,50.16 64.77,49.53 IC15.14
SR6  (via drill 0.61)
  Top 0.381: A40.32 71.12,8.26 69.85,9.53 69.85,18.41 71.12,19.68 R36.1 71.12,20.95 72.39,22.23 72.39,34.92 v71.12,36.2
  Bottom 0.381: v71.12,36.2 69.22,36.2 65.41,40.01 IC15.3
SR7  (via drill 0.61)
  Top 0.381: B40.6 104.14,8.26 102.87,9.53 102.87,18.41 104.14,19.68 R37.1 104.14,20.95 104.14,21.59 90.81,21.59 82.55,29.84 82.55,32.38 v77.47,37.47
  Bottom 0.381: v77.47,37.47 70.48,37.47 67.94,40.01 IC15.4
SR8  (via drill 0.61)
  Top 0.381: R38.1 106.68,19.68 105.41,18.41 105.41,9.53 106.68,8.26 B40.8 | v69.85,29.21 69.85,39.37 IC15.5
  Bottom 0.381: v69.85,29.21 77.47,21.59 104.78,21.59 106.05,20.32 R38.1
SR9  (via drill 0.61)
  Top 0.381: R39.1 109.22,19.68 107.95,18.41 107.95,9.53 109.22,8.26 B40.10 | v74.93,27.94 74.93,36.83 72.39,39.37 IC15.6
  Bottom 0.381: v74.93,27.94 80.01,22.86 106.05,22.86 108.58,20.32 R39.1
SR10
  Top 0.381: R40.1 111.76,19.68 110.49,18.41 110.49,9.53 111.76,8.26 B40.12 111.76,6.99 111.76,3.81 137.79,3.81 140.97,6.99 140.97,45.72 139.7,46.99 IC2.11
SR11
  Top 0.381: R41.1 114.3,19.68 113.03,18.41 113.03,9.53 114.3,8.26 B40.14 114.3,6.99 114.3,5.08 136.53,5.08 138.43,6.99 138.43,41.91 137.16,43.18 137.16,46.99 IC2.12
SS  (via drill 0.61)
  Top 0.381: v115.57,21.59 115.57,43.18 111.76,46.99 IC18.11
  Bottom 0.381: 139.7,19.05 139.7,11.43 139.06,11.43 138.43,10.79 138.43,8.26 139.7,8.26 B40.34 | 139.7,19.05 139.7,19.68 R48.1 | v115.57,21.59 115.57,19.05 139.7,19.05
SSER\  (via drill 0.61)  (1 unrouted)
  Top 0.381: v294.64,29.21 294.64,21.59 IC17.13 | v176.53,31.75 175.26,33.02 175.26,95.89 177.8,98.42 SV1.8 | v123.19,73.66 123.19,55.88 116.84,49.53 IC18.9 | v161.29,85.72 162.56,87 162.56,95.89 165.1,98.42 SV2.8
  Bottom 0.381: v294.64,29.21 259.71,29.21 254.63,24.13 253.37,24.13 252.73,23.5 252.73,21.59 245.11,21.59 234.95,31.75 v176.53,31.75 | v123.19,73.66 149.22,73.66 v161.29,85.72
START
  Top 0.381: R42.1 116.84,19.68 115.57,18.41 115.57,9.53 116.84,8.26 B40.16 116.84,6.99 116.84,6.35 122.56,6.35 123.19,6.99 123.19,26.04 133.35,36.2 133.35,45.72 134.62,46.99 IC2.13
STOP
  Top 0.381: B40.30 134.62,8.26 133.35,9.53 133.35,18.41 134.62,19.68 R47.1 134.62,20.95 135.89,22.23 135.89,50.16 137.79,50.16 138.43,49.53 138.43,43.18 139.7,41.91 IC2.6
TAD
  Top 0.381: R53.2 312.42,123.83 312.42,117.47 311.15,116.2 311.15,114.94 312.42,113.67 D40.4
TXD
  Top 0.381: IC3.14 231.78,19.68 233.04,19.68 IC3.13
  Bottom 0.381: X1.2 192.41,18.41 193.04,17.78 196.85,17.78 RS-232.2 199.39,17.78 210.19,17.78 214.63,22.23 229.24,22.23 230.5,20.95 IC3.14
VCC  (via drill 0.61)  (1 unrouted)
  Top 1.016: IC11.16 233.68,59.69 231.78,61.59 v231.78,65.41 231.78,70.48 233.68,72.39 233.68,74.93 IC12.16 | v254,63.5 254,57.78 C15.1 | v318.77,79.38 317.5,78.11 317.5,77.47 IC16.16 | v289.56,79.38 289.56,77.47 IC13.16 | v266.7,65.41 269.24,67.94 v269.24,74.93 | J1.4 354.33,93.34 v354.33,83.19 v354.33,64.14 | 5V.1 276.86,22.23 276.86,21.59 IC17.20 | IC19.9 321.94,19.68 320.68,19.68 IC19.10 320.04,21.59 v320.04,24.13 | IC19.14 310.51,19.68 311.79,19.68 IC19.13 313.06,19.68 314.32,19.68 IC19.12 314.96,21.59 v314.96,24.13 | C23.1 223.52,18.41 221.62,16.51 221.62,10.16 223.52,8.26 C1.1 | 203.84,32.38 203.84,13.97 207.01,10.79 +V1.1 | 203.84,32.38 203.84,54.61 205.74,56.52 C13.1 | v200.03,73.66 200.03,36.2 203.84,32.38 | v181.61,80.64 v181.61,91.44 | v335.28,62.23 334.01,60.96 v334.01,25.4 | v99.69,62.23 99.69,50.16 99.06,49.53 IC18.16 | IC7.16 132.08,64.77 127,59.69 127,49.53 IC2.16 | R47.2 133.99,30.48 132.72,30.48 R46.2 | R37.2 104.78,30.48 106.05,30.48 R38.2 107.31,30.48 108.58,30.48 R39.2 109.86,30.48 111.12,30.48 R40.2 | R42.2 117.47,30.48 118.75,30.48 R43.2 119.38,31.11 119.38,41.27 124.46,46.35 C22.1 | 32.07,51.12 32.38,51.44 57.15,51.44 57.15,47.62 C20.1 | 32.07,51.12 30.48,49.53 IC14.16 | R6.1 84.45,20.32 85.72,20.32 R50.1 87,20.32 88.27,20.32 R7.1 89.53,20.32 90.81,20.32 R8.1 92.08,20.32 93.34,20.32 R9.1 94.61,20.32 95.89,20.32 R10.1 | R26.2 42.55,30.48 41.27,30.48 R25.2 | R27.2 46.35,30.48 47.62,30.48 R28.2 48.9,30.48 50.16,30.48 R29.2 51.44,30.48 52.7,30.48 R30.2 | C18.1 152.4,65.41 154.31,67.31 154.31,82.55 152.4,84.45 C9.1 152.4,85.72 v152.4,89.53 | v132.08,89.53 132.08,87.63 IC8.16
  Top 1.016: v46.35,97.79 46.35,89.53 48.26,87.63 IC4.16 | v72.39,99.06 72.39,89.53 68.58,85.72 C7.1 | v106.68,89.53 106.68,87.63 IC6.16 | 32.07,51.12 31.75,51.44 18.41,64.77 18.41,82.55 20.32,84.45 C6.1
  Bottom 1.016: J1.4 356.87,93.34 367.67,93.34 +V2.1 | 253.68,63.82 252.09,65.41 v231.78,65.41 | 253.68,63.82 v254,63.5 | C11.1 254.63,74.93 v269.24,74.93 286.38,74.93 C12.1 287.65,74.93 288.29,74.93 288.93,75.56 IC13.16 | v289.56,79.38 v318.77,79.38 335.28,79.38 336.55,78.11 337.82,78.11 337.82,75.56 C14.1 338.45,74.93 346.07,74.93 v354.33,83.19 | v266.7,65.41 255.27,65.41 254,64.14 253.68,63.82 | IC17.20 276.23,19.68 275.59,19.68 274.95,19.05 C24.1 273.69,19.05 267.97,19.05 267.33,19.68 246.38,19.68 244.47,17.78 227.33,17.78 226.06,19.05 IC3.16 225.43,19.68 224.79,19.68 224.16,19.05 C23.1 | IC19.14 309.25,19.68 308.61,19.68 307.98,19.05 C17.1 306.7,19.05 305.44,19.05 301.62,22.86 277.5,22.86 5V.1 | v314.96,24.13 v320.04,24.13 332.74,24.13 v334.01,25.4 | IC10.16 207.65,75.56 207.01,75.56 206.38,74.93 C10.1 205.1,74.93 203.84,73.66 v200.03,73.66 188.59,73.66 v181.61,80.64 | C13.1 206.38,57.15 207.01,57.78 207.65,57.78 IC9.16 | C1.1 222.88,7.62 212.09,7.62 +V1.1 | v181.61,91.44 175.26,91.44 175.26,108.58 175.9,109.22 177.8,109.22 177.8,117.47 +V4.1 | v354.33,64.14 352.43,62.23 v335.28,62.23 | C21.1 97.16,46.99 97.79,47.62 98.42,47.62 IC18.16 | v99.69,62.23 102.23,64.77 103.5,64.77 C16.1 104.78,64.77 105.41,65.41 106.05,65.41 IC5.16 106.68,67.31 108.58,69.22 128.91,69.22 131.44,66.67 IC7.16 | C22.1 125.09,46.99 125.73,47.62 126.36,47.62 IC2.16 | R46.2 131.44,30.48 130.18,30.48 R45.2 128.91,30.48 122.56,30.48 R44.2 121.28,30.48 120.02,30.48 R43.2 | R47.2 135.25,30.48 136.53,30.48 R49.2 137.79,30.48 139.06,30.48 R48.2 | R40.2 112.39,30.48 113.67,30.48 R41.2 114.94,30.48 116.2,30.48 R42.2
  Bottom 1.016: IC14.16 29.84,47.62 29.21,47.62 28.57,46.99 C19.1 27.94,46.35 27.94,45.09 26.04,43.18 26.04,31.11 38.1,31.11 R24.2 38.73,30.48 40.01,30.48 R25.2 | C20.1 57.78,46.99 58.42,47.62 59.05,47.62 IC15.16 | R33.2 65.41,30.48 64.14,30.48 R32.2 62.87,30.48 56.52,30.48 R31.2 55.24,30.48 53.98,30.48 R30.2 | 66.67,30.48 67.94,30.48 R34.2 69.22,30.48 70.48,30.48 R36.2 71.75,30.48 73.03,30.48 R35.2 74.3,30.48 76.83,27.94 100.97,27.94 103.5,30.48 R37.2 | R33.2 66.67,30.48 | R27.2 45.09,30.48 43.81,30.48 R26.2 | 66.67,30.48 76.83,20.32 83.19,20.32 R6.1 | R33.2 66.67,30.48 | v152.4,89.53 v132.08,89.53 v106.68,89.53 | C7.1 69.22,85.09 103.5,85.09 C8.1 104.78,85.09 105.41,85.09 106.05,85.72 IC6.16 | C6.1 20.95,85.09 21.59,85.72 22.23,85.72 IC1.16 22.86,87.63 33.02,97.79 v46.35,97.79 47.62,99.06 v72.39,99.06 76.2,99.06 85.72,108.58 165.1,108.58 165.1,117.47 +V3.1
VDD  (via drill 0.61)
  Top 1.016: v269.24,22.86 v269.24,17.14 | v259.08,24.77 256.54,27.3 3.3V.2
  Bottom 1.016: v269.24,17.14 321.31,17.14 321.94,16.51 347.98,16.51 J4.4 | v269.24,22.86 267.33,24.77 v259.08,24.77
VSS  (via drill 0.61)
  Top 1.016: v341.63,4.45 346.07,8.89 v346.07,10.16
  Bottom 1.016: J4.3 348.62,19.68 349.88,19.68 349.88,12.06 349.25,11.43 348.62,11.43 J4.6 347.98,10.79 346.71,10.79 v346.07,10.16 | v341.63,4.45 338.45,1.27 269.24,1.27 264.8,5.71 252.73,5.71 252.09,5.08 J3.1
WC
  Bottom 0.381: R64.2 340.36,123.83 340.36,120.02 344.17,116.2 344.17,113.67 345.44,113.67 D40.30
